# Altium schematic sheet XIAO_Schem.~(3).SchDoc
size A; SheetNumber: 1; SheetTotal: 1
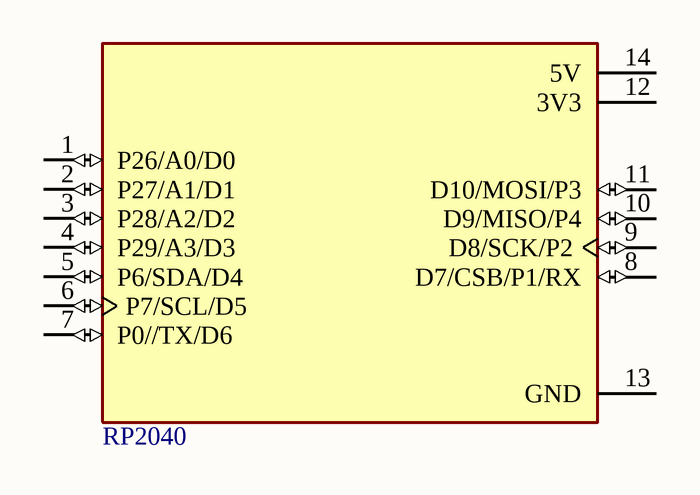
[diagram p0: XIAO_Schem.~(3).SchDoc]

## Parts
RP2040  102010428  [102010428]  (value not drawn)

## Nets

Not connected (* = marked no-connect by the designer): RP2040 1(P26/A0/D0) 2(P27/A1/D1) 3(P28/A2/D2) 4(P29/A3/D3) 5(P6/SDA/D4) 6(P7/SCL/D5) 7(P0//TX/D6) 8(D7/CSB/P1/RX) 9(D8/SCK/P2) 10(D9/MISO/P4) 11(D10/MOSI/P3) 12(3V3) 13(GND) 14(5V)

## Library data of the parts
RP2040 = 102010428: RP2040 XIAO RP2040 series ARMÂ® CortexÂ®-M0+ MCU 32-Bit Embedded Evaluation Board; MF: Seeed Technology Co., Ltd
